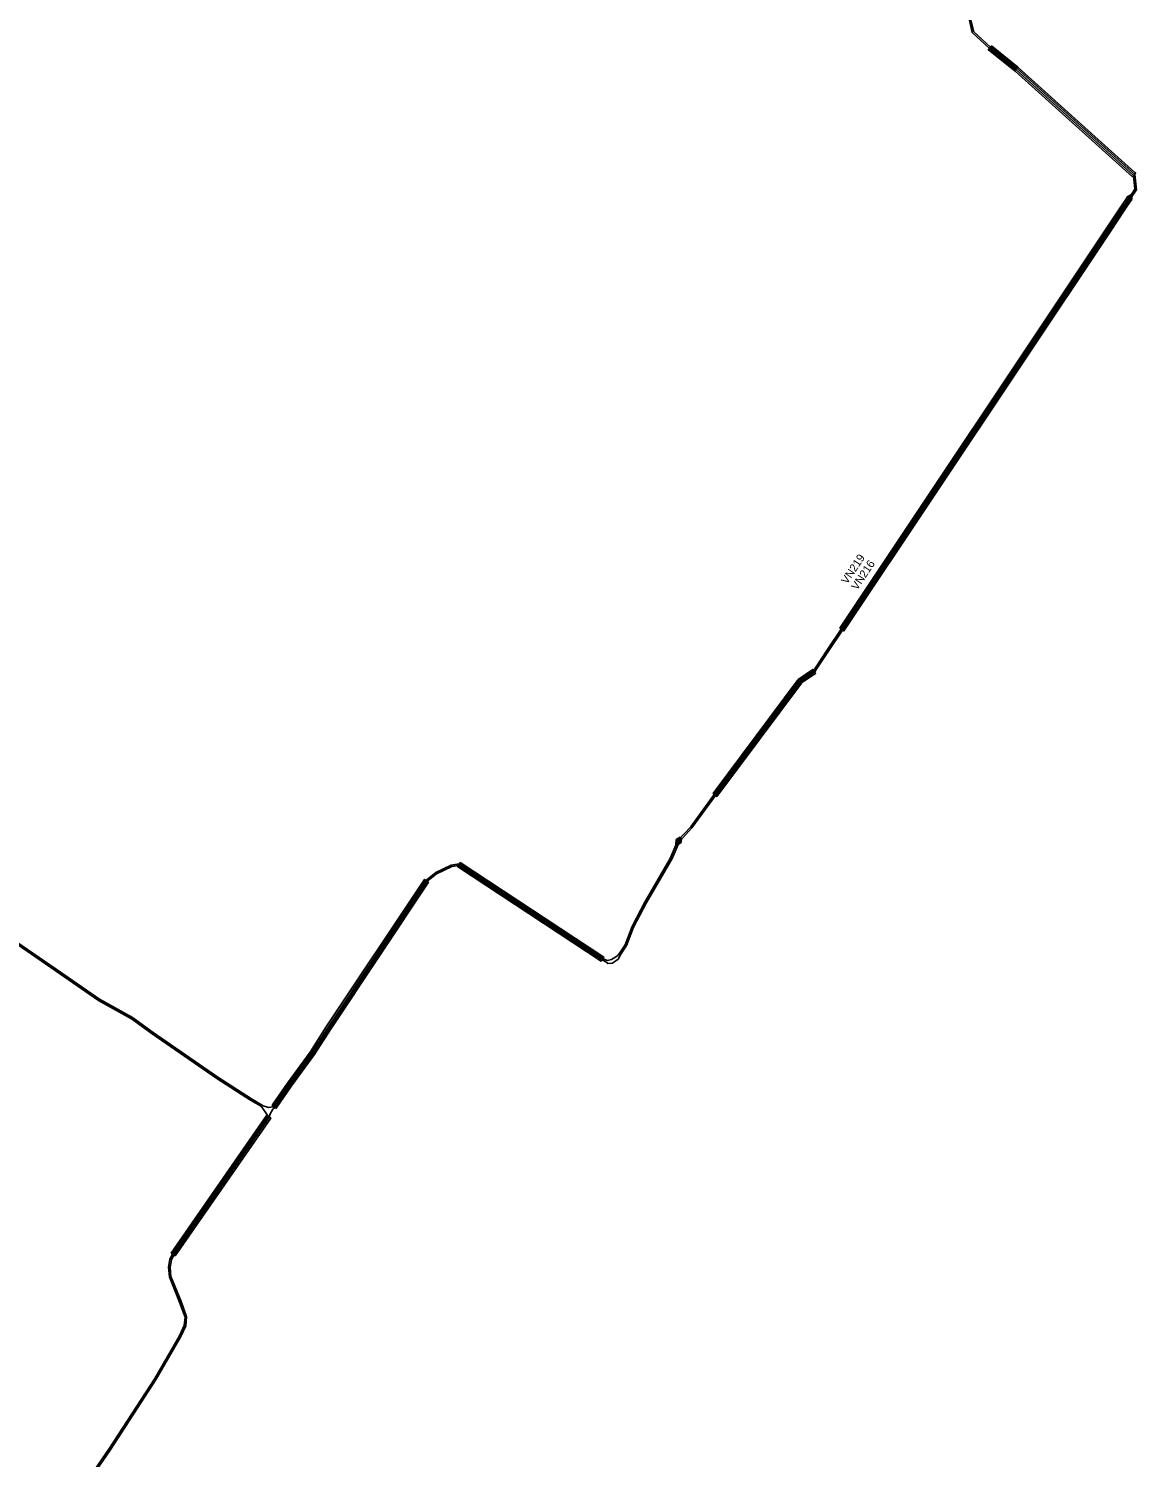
# Model space of a CAD drawing. Extents: x -643811 to -636362, y -1117362 to -1108614.
# Drawn here: x -641726.5 to -641588.8, y -1116043.8 to -1115866.2 of the extents above; entities that cross this region are included whole.
import ezdxf

# ---------------------------------------------------------------- set-up
doc = ezdxf.new("R2010")
doc.units = 0
for name, color, linetype in [('19', 7, 'Continuous'), ('20', 7, 'Continuous'), ('5', 7, 'Continuous'), ('7', 7, 'Continuous')]:
    doc.layers.add(name, color=color, linetype=linetype)

# ---------------------------------------------------------------- blocks, each defined once
blk = doc.blocks.new('VN870')
at = {"layer": '19'}
for points in [[(0, -0.25), (0.5, 0), (0, 0.25), (-0.5, 0), (0, -0.25)], [(0.37, 0), (0, 0.19), (-0.36, 0), (0, -0.19), (0.37, 0)], [(0.24, 0), (0, 0.12), (-0.25, 0), (0, -0.12), (0.24, 0)], [(0.12, 0), (0, 0.06), (-0.13, 0), (0, -0.06), (0.12, 0)]]:
    blk.add_lwpolyline(points, dxfattribs=at)

msp = doc.modelspace()

# ---------------------------------------------------------------- linework, layer by layer
at = {"layer": '20'}
for points in [[(-641606.86, -1115868.38), (-641603.57, -1115871.02), (-641603.52, -1115871.06), (-641589.04, -1115884.1), (-641588.92, -1115884.21), (-641589.32, -1115884.65), (-641603.9, -1115871.52), (-641607.24, -1115868.84)], [(-641625.68, -1115940.73), (-641592.53, -1115891.01), (-641590.76, -1115888.39), (-641589.97, -1115887.22), (-641589.64, -1115887.45), (-641589.47, -1115887.56), (-641590.26, -1115888.73), (-641592.03, -1115891.35), (-641625.18, -1115941.07), (-641625.35, -1115940.96)], [(-641641.12, -1115961.51), (-641641.44, -1115961.27), (-641630.85, -1115947.1), (-641629.03, -1115945.85), (-641628.69, -1115946.35), (-641630.43, -1115947.54), (-641630.44, -1115947.55), (-641640.96, -1115961.63)], [(-641672.84, -1115969.85), (-641655.01, -1115981.59), (-641655.12, -1115981.76), (-641655.33, -1115982.09), (-641673.17, -1115970.35), (-641672.95, -1115970.02)], [(-641696.15, -1115999.97), (-641694.29, -1115997.25), (-641691.47, -1115993.41), (-641689.48, -1115990.28), (-641677.3, -1115971.96), (-641677.13, -1115972.07), (-641676.8, -1115972.3), (-641688.98, -1115990.6), (-641690.97, -1115993.75), (-641693.81, -1115997.59), (-641695.7, -1116000.37), (-641696.2, -1116000.03)], [(-641708.76, -1116018.37), (-641696.88, -1116001.25), (-641696.38, -1116001.59), (-641708.26, -1116018.71)]]:
    msp.add_lwpolyline(points, close=True, dxfattribs=at)
at = {"layer": '5'}
for points in [[(-641730.19, -1115978.2), (-641723.05, -1115983.11), (-641717.67, -1115986.82), (-641713.57, -1115989.09), (-641710.99, -1115990.98), (-641702.96, -1115996.51), (-641698.79, -1115999.2), (-641697.31, -1116000.07), (-641696.66, -1116000.27), (-641696.08, -1116000.21), (-641694.13, -1115997.36), (-641691.3, -1115993.52), (-641689.31, -1115990.39), (-641677.12, -1115972.06), (-641675.89, -1115971.07), (-641673.95, -1115970.16), (-641672.98, -1115969.99), (-641655.12, -1115981.76), (-641654.8, -1115981.94), (-641654.56, -1115982), (-641654.07, -1115981.9), (-641653.32, -1115981.43), (-641652.93, -1115980.95), (-641652.36, -1115980.09), (-641651.48, -1115977.8), (-641649.91, -1115974.78), (-641646.75, -1115969.36), (-641645.8, -1115967.13), (-641644.21, -1115965.41), (-641641.28, -1115961.39), (-641630.71, -1115947.25), (-641628.93, -1115946.03), (-641628.71, -1115945.66), (-641627.21, -1115943.38), (-641625.51, -1115940.84), (-641592.36, -1115891.12), (-641590.59, -1115888.5), (-641589.8, -1115887.33), (-641589.04, -1115886.2), (-641589.22, -1115884.48), (-641603.77, -1115871.37), (-641607.12, -1115868.69), (-641609.23, -1115866.74), (-641609.59, -1115865.2)], [(-641609.39, -1115865.21), (-641609.05, -1115866.64), (-641606.98, -1115868.53), (-641603.65, -1115871.21), (-641589.02, -1115884.38), (-641588.84, -1115886.26), (-641589.64, -1115887.45), (-641590.43, -1115888.62), (-641592.2, -1115891.24), (-641625.35, -1115940.96), (-641627.05, -1115943.5), (-641628.55, -1115945.76), (-641628.79, -1115946.17), (-641630.57, -1115947.39), (-641641.12, -1115961.51), (-641644.05, -1115965.53), (-641645.62, -1115967.25), (-641646.57, -1115969.45), (-641649.73, -1115974.88), (-641651.3, -1115977.88), (-641652.18, -1115980.17), (-641652.87, -1115981.23), (-641653.23, -1115981.87), (-641653.93, -1115982.36), (-641654.5, -1115982.41), (-641654.76, -1115982.19), (-641655.22, -1115981.92), (-641673.02, -1115970.21), (-641673.89, -1115970.36), (-641675.79, -1115971.25), (-641676.98, -1115972.2), (-641689.15, -1115990.49), (-641691.14, -1115993.64), (-641693.97, -1115997.48), (-641695.91, -1116000.33), (-641696.12, -1116000.5), (-641696.48, -1116001.15), (-641696.53, -1116001.45), (-641708.42, -1116018.59), (-641708.72, -1116019.19), (-641708.89, -1116020.12), (-641708.78, -1116021.28), (-641707.52, -1116024.37), (-641706.83, -1116026.3), (-641706.94, -1116027.42), (-641707.54, -1116028.73), (-641710.61, -1116034.05), (-641716.32, -1116042.84), (-641722.85, -1116052.3)], [(-641723.01, -1116052.18), (-641716.48, -1116042.72), (-641710.79, -1116033.95), (-641707.72, -1116028.63), (-641707.14, -1116027.36), (-641707.03, -1116026.32), (-641707.7, -1116024.45), (-641708.98, -1116021.32), (-641709.09, -1116020.12), (-641708.92, -1116019.13), (-641708.6, -1116018.49), (-641696.69, -1116001.34), (-641697.59, -1116000.13), (-641698.89, -1115999.38), (-641703.08, -1115996.67), (-641711.11, -1115991.14), (-641713.67, -1115989.25), (-641717.77, -1115987), (-641723.17, -1115983.27), (-641730.29, -1115978.36)]]:
    msp.add_lwpolyline(points, dxfattribs=at)

# ---------------------------------------------------------------- block references
at = {"layer": '19'}
for p, rotation in [((-641589.8, -1115887.33), 57), ((-641589.64, -1115887.45), 57), ((-641645.8, -1115967.13), 58.00000000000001), ((-641645.62, -1115967.25), 58.99999999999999)]:
    msp.add_blockref('VN870', p, dxfattribs=dict(at, rotation=rotation))

# ---------------------------------------------------------------- texts
at = {"layer": '7'}
for s, p in [('VN219', (-641624.77, -1115935.34)), ('VN216', (-641623.53, -1115936.09))]:
    msp.add_text(s, height=0.994, rotation=56.3073, dxfattribs=at).set_placement(p)

doc.saveas('drawing.dxf')
